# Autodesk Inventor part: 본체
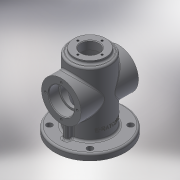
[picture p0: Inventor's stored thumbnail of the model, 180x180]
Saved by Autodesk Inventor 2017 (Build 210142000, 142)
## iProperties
Created: 2020-05
Part Number: 본체
Material: 알루미늄 6061
Document SubType Name: Modeling
Designer: mduedu
Density: 2.71 g/cm^3
Mass: 777.255 g
Surface Area: 687.925 cm^2
Volume: 286.81 cm^3
Appearance: 기본값
Author: mduedu
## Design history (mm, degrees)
sketch "스케치1"
  geometry: C1 r 32 at (0, 0); 1 further point
  constraints: 1 centre point, 1 coincident
  dimensions: "d0" = 64 diameter of C1
extrude "돌출1" new body sketch "스케치1" distance "d1" = 110; taper "d2" = 0 deg
feature "쉘1" dims "d3" = 8
fillet "모깎기1" dims "d4" = 3
fillet "모깎기2" dims "d5" = 3
sketch "스케치2"
  geometry: C1 r 25 at (0, 0); 1 further point
  constraints: 1 centre point, 1 coincident
  dimensions: "d6" = 50 diameter of C1
extrude "돌출2" join sketch "스케치2" distance "d7" = 5; taper "d8" = 0 deg
sketch "스케치3"
  geometry: C1 r 14 at (0, 0); 1 further point
  constraints: 1 centre point, 1 coincident
  dimensions: "d9" = 28 diameter of C1
extrude "돌출3" cut sketch "스케치3" stored distance "d10" = 5; taper "d11" = 0 deg
fillet "모깎기3" dims "d12" = 3
sketch "스케치4"
  geometry: C1 r 32 at (0, 0) reference; C2 r 55 at (0, 0); 1 further point
  constraints: 1 centre point, 1 coincident
  dimensions: "d13" = 110 diameter of C2
extrude "돌출4" join sketch "스케치4" distance "d14" = 10; taper "d15" = 0 deg
sketch "스케치5"
  geometry: L1 (0, 0)-(-31.82, 31.82); L2 (0, 0)-(-45, 0); A1 r 45 centre (0, 0) between (-31.82, 31.82) and (-45, 0); 1 further point
  constraints: 4 end point, 2 point on circle, 1 centre point, 1 coincident, 1 horizontal
  dimensions: "d16" = 90 diameter of A1; "d71" = 45 deg angle of L1 L2
hole "구멍1" sketch "스케치5" at (-31.82, 31.82) diameter "d17" = 9; stored, may be unused: countersink angle "d21" = 90 deg, drill point angle "d23" = 118 deg; dims "d18" = 6, "d19" = 4, "d20" = 2, "d22" = 8
fillet "모깎기4" dims "d27" = 3
node "작업 평면1"
sketch "스케치6"
  geometry: L1 (0, 55)-(0, -55) reference; C1 r 31 at (-65, 0); 2 further points
  constraints: 1 centre point, 1 horizontal alignment, 1 midpoint
  dimensions: "d31" = 62 diameter of C1; "d32" = 65 distance from line of C1.centre L1
extrude "돌출5" join sketch "스케치6" stored distance "d33" = 10; taper "d34" = 0 deg
fillet "모깎기5" dims "d35" = 3
sketch "스케치7"
  geometry: C1 r 31 at (0, 0) reference; C2 r 20 at (0, 0); 1 further point
  constraints: 1 centre point, 1 coincident
  dimensions: "d36" = 40 diameter of C2
extrude "돌출6" cut sketch "스케치7" distance "d37" = 16; taper "d38" = 0 deg
sketch "스케치8"
  geometry: C1 r 20 at (0, 0) reference; C2 r 17 at (0, 0); 1 further point
  constraints: 1 centre point, 1 coincident
  dimensions: "d39" = 34 diameter of C2
extrude "돌출7" cut sketch "스케치8" stored distance "d40" = 15; taper "d41" = 0 deg
fillet "모깎기6" dims "d42" = 0.3
chamfer "모따기1" distance "d43" = 1; stored, may be unused: second distance "d44" = 2, angle "d45" = 45 deg
chamfer "모따기2" distance "d46" = 1; stored, may be unused: second distance "d47" = 2, angle "d48" = 45 deg
sketch "스케치9" dims "d49" = 50
  geometry: C1 r 31 at (0, 0) reference; 3 further points
  constraints: 2 vertical alignment, 1 coincident, 2 other
hole "구멍2" sketch "스케치9" at (0, 25) diameter "d50" = 3.242; stored, may be unused: countersink angle "d54" = 90 deg, drill point angle "d56" = 118 deg; dims "d51" = 7, "d52" = 4, "d53" = 2, "d55" = 9
sketch "스케치10" dims "d60" = 38
  geometry: 3 further points
  constraints: 2 vertical alignment, 1 coincident, 2 other
hole "구멍3" sketch "스케치10" at (0, 19) diameter "d61" = 3.242; stored, may be unused: countersink angle "d65" = 90 deg, drill point angle "d67" = 118 deg; dims "d62" = 8, "d63" = 4, "d64" = 2, "d66" = 10
sketch "스케치11"
  geometry: L1 (32, 31)-(32, 13) reference; L2 (35, 10)-(52, 10) reference; L3 (55, 7)-(55, 0) reference; L4 (55, 0)-(24, 0) reference; L5 (24, 0)-(24, 48) reference; L6 (24, 48)-(29, 48) reference; L7 (29, 48)-(29, 45.3) reference; L8 (29.3, 45)-(44, 45) reference; L9 (44, 45)-(45, 44) reference; L10 (45, 44)-(45, 41.621) reference; L11 (45, 41.621)-(36, 41.621) reference; L12 (36, 41.621)-(35.026, 40) reference; L13 (35.026, 40)-(36, 38.379) reference; L14 (36, 38.379)-(45, 38.379) reference; L15 (45, 38.379)-(45, 34) reference; L16 (45, 34)-(35, 34) reference; L17 (-32, 13)-(-32, 31) reference; L18 (-35, 34)-(-45, 34) reference; L19 (-45, 34)-(-45, 38.379) reference; L20 (-45, 38.379)-(-36, 38.379) reference; L21 (-36, 38.379)-(-35.026, 40) reference; L22 (-35.026, 40)-(-36, 41.621) reference; L23 (-36, 41.621)-(-45, 41.621) reference; L24 (-45, 41.621)-(-45, 44) reference; L25 (-45, 44)-(-44, 45) reference; L26 (-44, 45)-(-29.3, 45) reference; L27 (-29, 45.3)-(-29, 48) reference; L28 (-29, 48)-(-24, 48) reference; L29 (-24, 48)-(-24, 0) reference; L30 (-24, 0)-(-55, 0) reference; L31 (-55, 0)-(-55, 7) reference; L32 (-52, 10)-(-35, 10) reference; L33 (-25, 113)-(-25, 115) reference; L34 (-25, 115)-(-20.621, 115) reference; L35 (-20.621, 115)-(-20.621, 105) reference; L36 (-20.621, 105)-(-19, 104.026) reference; L37 (-19, 104.026)-(-17.379, 105) reference; L38 (-17.379, 105)-(-17.379, 115) reference; L39 (-17.379, 115)-(-15, 115) reference; L40 (-15, 115)-(-14, 114) reference; L41 (-14, 114)-(-14, 102) reference; L42 (-14, 102)-(-21, 102) reference; L43 (-24, 99)-(-24, 82) reference; L44 (-24, 82)-(-29, 82) reference; L45 (-29, 82)-(-29, 84.7) reference; L46 (-29.3, 85)-(-44, 85) reference; L47 (-44, 85)-(-45, 86) reference; L48 (-45, 86)-(-45, 88.379) reference; L49 (-45, 88.379)-(-36, 88.379) reference; L50 (-36, 88.379)-(-35.026, 90) reference; L51 (-35.026, 90)-(-36, 91.621) reference; L52 (-36, 91.621)-(-45, 91.621) reference; L53 (-45, 91.621)-(-45, 96) reference; L54 (-45, 96)-(-35, 96) reference; L55 (-32, 99)-(-32, 107) reference; L56 (-29, 110)-(-28, 110) reference; L57 (28, 110)-(29, 110) reference; L58 (32, 107)-(32, 99) reference; L59 (35, 96)-(45, 96) reference; L60 (45, 96)-(45, 91.621) reference; L61 (45, 91.621)-(36, 91.621) reference; L62 (36, 91.621)-(35.026, 90) reference; L63 (35.026, 90)-(36, 88.379) reference; L64 (36, 88.379)-(45, 88.379) reference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; A1 r 3 centre (35, 13) between (32, 13) and (35, 10) reference; A2 r 3 centre (52, 7) between (55, 7) and (52, 10) reference; A3 r 0.3 centre (29.3, 45.3) between (29, 45.3) and (29.3, 45) reference; A4 r 0.3 centre (-29.3, 45.3) between (-29.3, 45) and (-29, 45.3) reference; A5 r 3 centre (-52, 7) between (-52, 10) and (-55, 7) reference; A6 r 3 centre (-35, 13) between (-35, 10) and (-32, 13) reference; A7 r 3 centre (-28, 113) between (-28, 110) and (-25, 113) reference; A8 r 3 centre (-21, 99) between (-21, 102) and (-24, 99) reference; A9 r 0.3 centre (-29.3, 84.7) between (-29, 84.7) and (-29.3, 85) reference; A10 r 3 centre (-29, 107) between (-29, 110) and (-32, 107) reference; A11 r 3 centre (28, 113) between (25, 113) and (28, 110) reference; A12 r 3 centre (29, 107) between (32, 107) and (29, 110) reference; A13 r 0.3 centre (29.3, 84.7) between (29.3, 85) and (29, 84.7) reference; A14 r 3 centre (21, 99) between (24, 99) and (21, 102) reference; 1 further point
  constraints: 2 end point, 1 midpoint, 1 perpendicular, 1 point on line, 4 other
  dimensions: "d73" = 5 distance between parallel lines of L81 L19
feature "리브1" sketch "스케치11" dims "d74" = 1, "d75" = 8, "d76" = 0, "d77" = 0, "d78" = 1, "d79" = 1
fillet "모깎기7" dims "d80" = 3
fillet "모깎기8" dims "d81" = 3
node "작업 평면2"
sketch "스케치12"
  geometry: 2 further points
  constraints: 1 vertical alignment, 1 other
  dimensions: "d83" = 25 distance of point (0, 25) point (0, 0)
feature "엠보싱1" sketch "스케치12" dims "d0" = 64, "d84" = 0.5, "d85" = 0
node "솔리드1"
pattern_circular "원형 패턴1" dims angle "d25" = 360 deg
mirror "대칭1"
mirror "대칭2"
pattern_circular "원형 패턴2" dims angle "d58" = 360 deg
mirror "대칭3"
pattern_circular "원형 패턴3" dims angle "d69" = 360 deg
mirror "대칭4"
node "투영된 루프1"
node "투영된 루프2"
node "절단 모서리 투영1"
other parameters: "d30" = -45
